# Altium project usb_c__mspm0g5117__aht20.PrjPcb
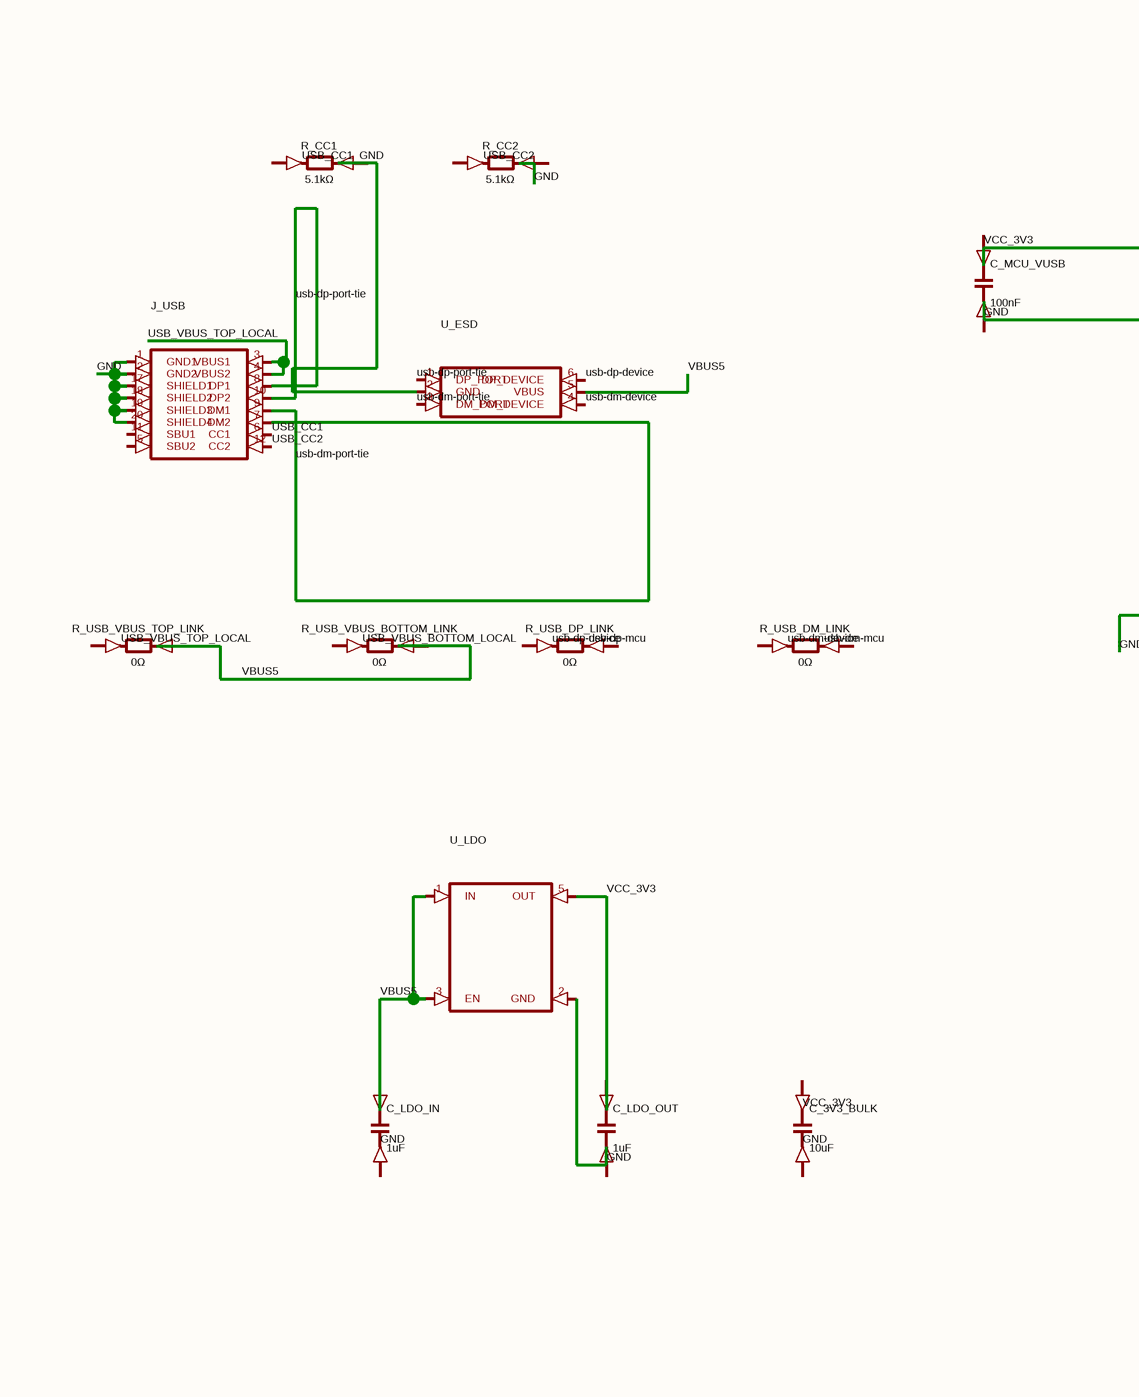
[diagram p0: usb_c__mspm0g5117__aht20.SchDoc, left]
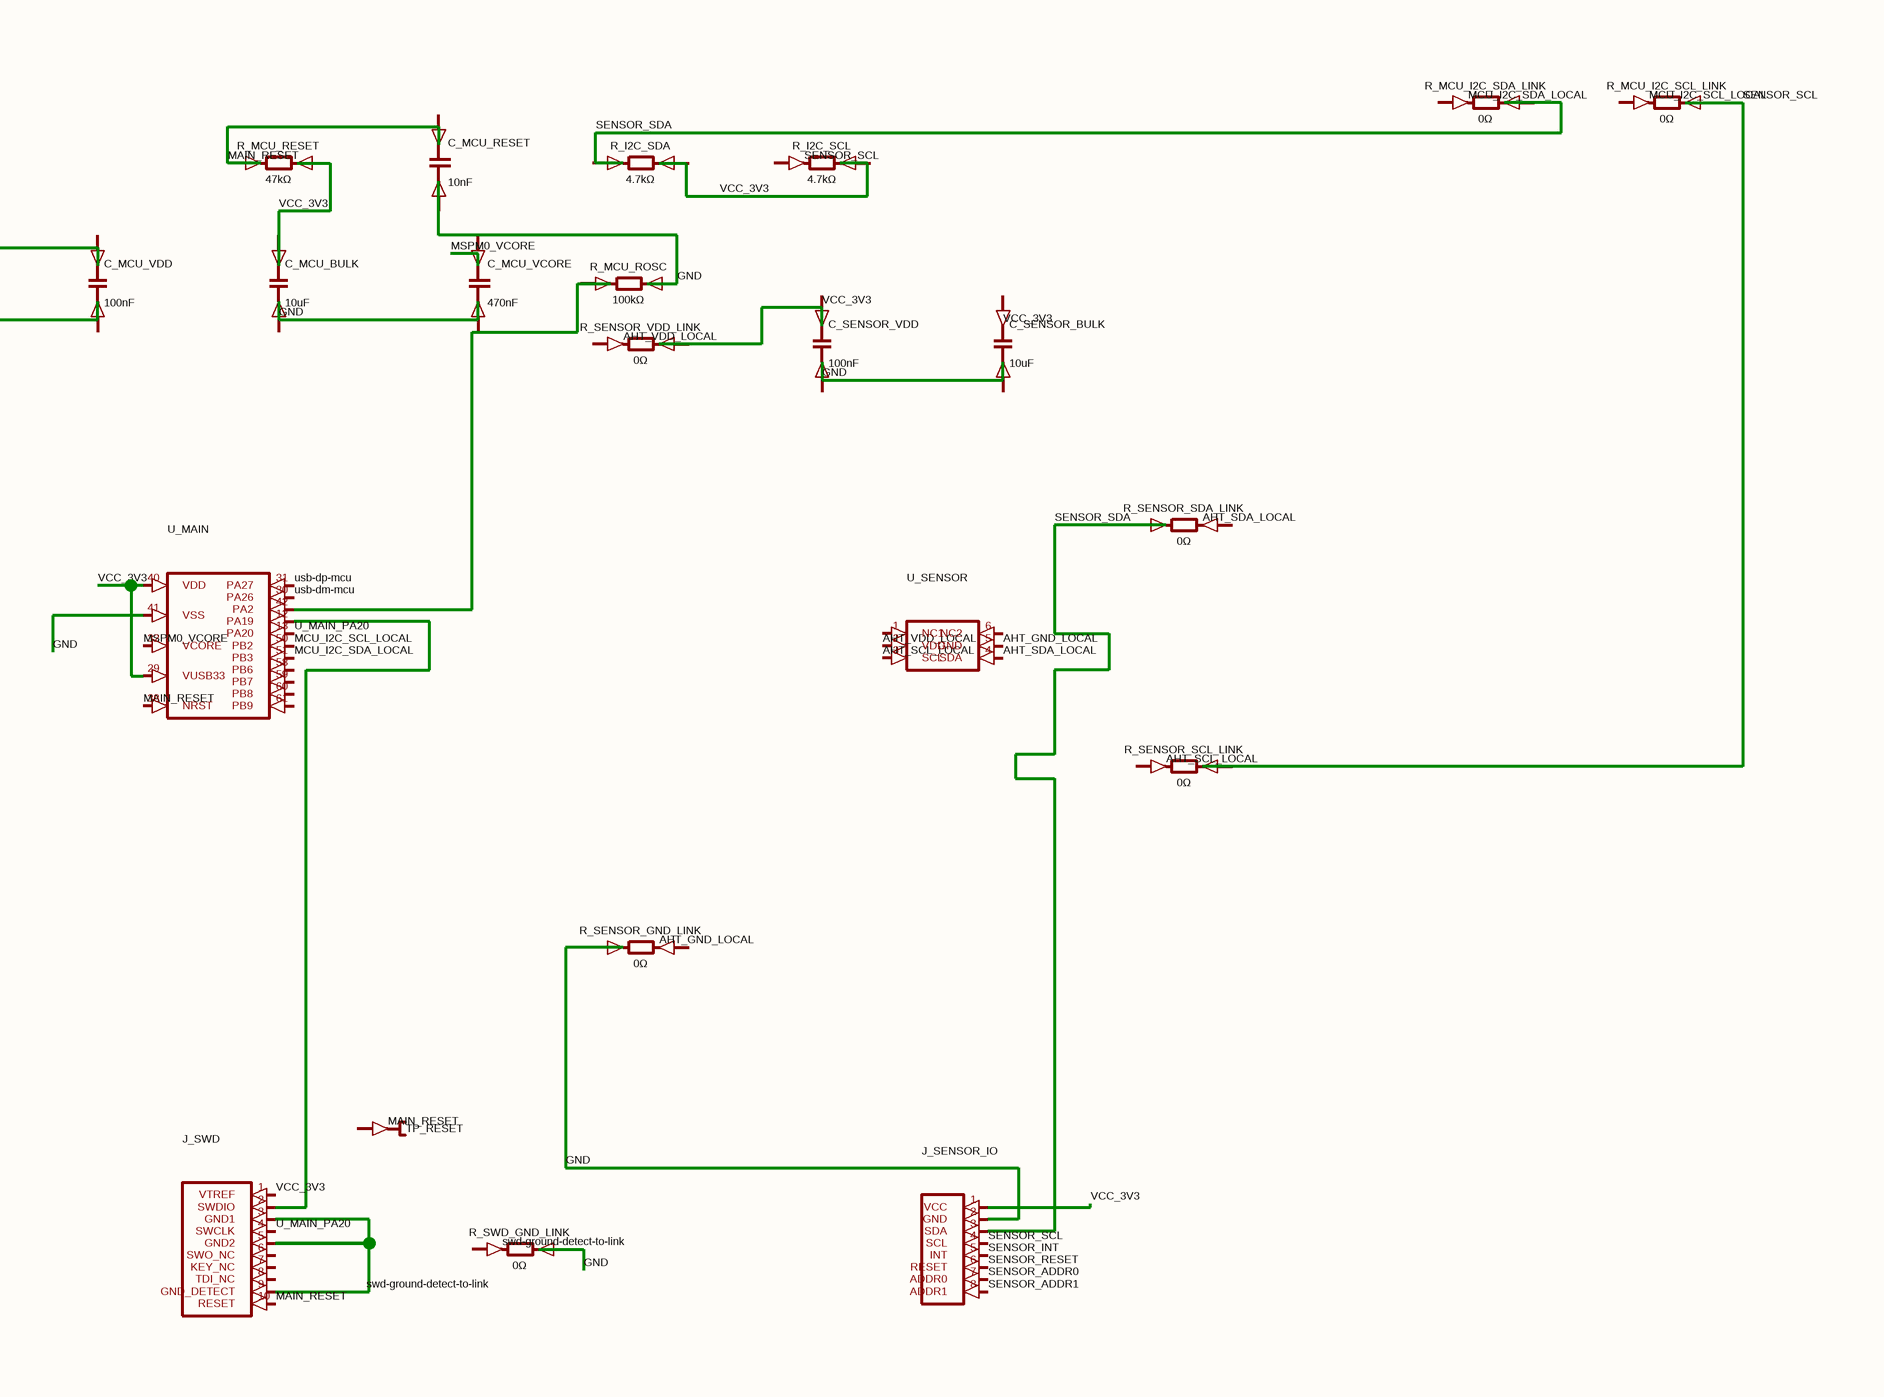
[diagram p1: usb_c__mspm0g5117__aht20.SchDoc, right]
1 sheet, 35 parts. Net scope: global (net labels, ports and power ports of the same name join across sheets).
Board file: usb_c__mspm0g5117__aht20.PcbDoc

## Sheet usb_c__mspm0g5117__aht20.SchDoc
size 286 x 151 mm

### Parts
C_3V3_BULK  10uF
C_LDO_IN  1uF
C_LDO_OUT  1uF
C_MCU_BULK  10uF
C_MCU_RESET  10nF
C_MCU_VCORE  470nF
C_MCU_VDD  100nF
C_MCU_VUSB  100nF
C_SENSOR_BULK  10uF
C_SENSOR_VDD  100nF
J_SENSOR_IO  (no value)
J_SWD  (no value)
J_USB  (no value)
R_CC1  5.1kΩ
R_CC2  5.1kΩ
R_I2C_SCL  4.7kΩ
R_I2C_SDA  4.7kΩ
R_MCU_I2C_SCL_LINK  0Ω
R_MCU_I2C_SDA_LINK  0Ω
R_MCU_RESET  47kΩ
R_MCU_ROSC  100kΩ
R_SENSOR_GND_LINK  0Ω
R_SENSOR_SCL_LINK  0Ω
R_SENSOR_SDA_LINK  0Ω
R_SENSOR_VDD_LINK  0Ω
R_SWD_GND_LINK  0Ω
R_USB_DM_LINK  0Ω
R_USB_DP_LINK  0Ω
R_USB_VBUS_BOTTOM_LINK  0Ω
R_USB_VBUS_TOP_LINK  0Ω
TP_RESET  (no value)
U_ESD  (no value)
U_LDO  (no value)
U_MAIN  (no value)
U_SENSOR  (no value)

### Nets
AHT_GND_LOCAL: U_SENSOR.5(GND)
AHT_SCL_LOCAL: U_SENSOR.3(SCL)
AHT_SDA_LOCAL: U_SENSOR.4(SDA)
AHT_VDD_LOCAL: U_SENSOR.2(VDD)
GND: C_LDO_OUT.1(anode) C_MCU_BULK.1(anode) C_MCU_RESET.2(cathode) C_MCU_VCORE.1(anode) J_SENSOR_IO.1(VCC) J_SENSOR_IO.2(GND) J_SWD.1(VTREF) J_USB.1(GND1) J_USB.2(GND2) J_USB.8(DP1) J_USB.10(DP2) J_USB.17(SHIELD1) J_USB.18(SHIELD2) J_USB.19(SHIELD3) J_USB.20(SHIELD4) R_CC1.2(cathode) R_MCU_RESET.2(cathode) R_MCU_ROSC.2(cathode) R_SENSOR_GND_LINK.1(anode) R_SENSOR_VDD_LINK.2(cathode) R_SWD_GND_LINK.2(cathode) U_ESD.1(DP_PORT) U_ESD.2(GND) U_LDO.2(GND) U_LDO.5(OUT) U_MAIN.29(VUSB33) U_MAIN.40(VDD) U_MAIN.41(VSS)  [also labelled usb-dp-port-tie, VCC_3V3]
MAIN_RESET: J_SWD.10(RESET) R_MCU_RESET.1(anode) U_MAIN.38(NRST)
MCU_I2C_SCL_LOCAL: U_MAIN.50(PB2)
MCU_I2C_SDA_LOCAL: U_MAIN.51(PB3)
MSPM0_VCORE: U_MAIN.32(VCORE)
SENSOR_ADDR0: J_SENSOR_IO.7(ADDR0)
SENSOR_ADDR1: J_SENSOR_IO.8(ADDR1)
SENSOR_INT: J_SENSOR_IO.5(INT)
SENSOR_RESET: J_SENSOR_IO.6(RESET)
SENSOR_SCL: J_SENSOR_IO.4(SCL) R_MCU_I2C_SCL_LINK.2(cathode) R_SENSOR_SCL_LINK.2(cathode)
SENSOR_SDA: J_SENSOR_IO.3(SDA) R_MCU_I2C_SDA_LINK.2(cathode) R_SENSOR_SDA_LINK.1(anode)
swd-ground-detect-to-link: J_SWD.3(GND1) J_SWD.5(GND2) J_SWD.9(GND_DETECT)
U_MAIN_PA20: J_SWD.4(SWCLK) U_MAIN.13(PA20)
usb-dm-device: U_ESD.4(DM_DEVICE)
usb-dm-mcu: U_MAIN.30(PA26)
usb-dm-port-tie: J_USB.7(DM2) J_USB.9(DM1) U_ESD.3(DM_PORT)
usb-dp-device: U_ESD.6(DP_DEVICE)
usb-dp-mcu: U_MAIN.31(PA27)
USB_CC1: J_USB.6(CC1)
USB_CC2: J_USB.12(CC2)
USB_VBUS_TOP_LOCAL: J_USB.3(VBUS1) J_USB.4(VBUS2)
VBUS5: C_LDO_IN.1(anode) R_USB_VBUS_BOTTOM_LINK.2(cathode) R_USB_VBUS_TOP_LINK.2(cathode) U_ESD.5(VBUS) U_LDO.1(IN) U_LDO.3(EN)
NetC_MCU_VCORE_2: C_MCU_VCORE.2(cathode) R_MCU_ROSC.1(anode) U_MAIN.42(PA2)
NetJ_SWD_2: J_SWD.2(SWDIO) U_MAIN.12(PA19)

Not connected (* = marked no-connect by the designer): C_3V3_BULK 1(anode) 2(cathode); C_LDO_IN 2(cathode); C_LDO_OUT 2(cathode); C_MCU_BULK 2(cathode); C_MCU_RESET 1(anode); C_MCU_VDD 1(anode) 2(cathode); C_MCU_VUSB 1(anode) 2(cathode); C_SENSOR_BULK 1(anode) 2(cathode); C_SENSOR_VDD 1(anode) 2(cathode); J_SWD 6(SWO_NC) 7(KEY_NC) 8(TDI_NC); J_USB 5(SBU2) 11(SBU1); R_CC1 1(anode); R_CC2 1(anode) 2(cathode); R_I2C_SCL 1(anode) 2(cathode); R_I2C_SDA 1(anode) 2(cathode); R_MCU_I2C_SCL_LINK 1(anode); R_MCU_I2C_SDA_LINK 1(anode); R_SENSOR_GND_LINK 2(cathode); R_SENSOR_SCL_LINK 1(anode); R_SENSOR_SDA_LINK 2(cathode); R_SENSOR_VDD_LINK 1(anode); R_SWD_GND_LINK 1(anode); R_USB_DM_LINK 1(anode) 2(cathode); R_USB_DP_LINK 1(anode) 2(cathode); R_USB_VBUS_BOTTOM_LINK 1(anode); R_USB_VBUS_TOP_LINK 1(anode); TP_RESET 1(pin1); U_MAIN 58(PB6) 59(PB7) 60(PB8) 61(PB9); U_SENSOR 1(NC1) 6(NC2)

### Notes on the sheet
- Labels drawn without touching a wire or pin: AHT_GND_LOCAL, AHT_SCL_LOCAL, AHT_SDA_LOCAL, AHT_VDD_LOCAL, GND, MAIN_RESET, MCU_I2C_SCL_LOCAL, MCU_I2C_SDA_LOCAL, SENSOR_SCL, swd-ground-detect-to-link, usb-dm-device, usb-dm-mcu, usb-dp-device, usb-dp-mcu, USB_CC1, USB_CC2, USB_VBUS_BOTTOM_LOCAL, USB_VBUS_TOP_LOCAL, VCC_3V3

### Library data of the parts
C_3V3_BULK C_LDO_IN C_LDO_OUT C_MCU_BULK C_MCU_RESET C_MCU_VCORE C_MCU_VDD C_MCU_VUSB C_SENSOR_BULK C_SENSOR_VDD = capacitor_down
J_SENSOR_IO = J_SENSOR_IO
J_SWD = J_SWD
J_USB = J_USB
R_CC1 R_CC2 R_I2C_SCL R_I2C_SDA R_MCU_I2C_SCL_LINK R_MCU_I2C_SDA_LINK R_MCU_RESET R_MCU_ROSC R_SENSOR_GND_LINK R_SENSOR_SCL_LINK R_SENSOR_SDA_LINK R_SENSOR_VDD_LINK R_SWD_GND_LINK R_USB_DM_LINK R_USB_DP_LINK R_USB_VBUS_BOTTOM_LINK R_USB_VBUS_TOP_LINK = boxresistor_right
TP_RESET = testpoint_right
U_ESD = U_ESD
U_LDO = U_LDO
U_MAIN = U_MAIN
U_SENSOR = U_SENSOR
